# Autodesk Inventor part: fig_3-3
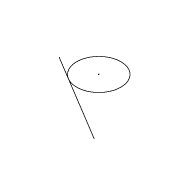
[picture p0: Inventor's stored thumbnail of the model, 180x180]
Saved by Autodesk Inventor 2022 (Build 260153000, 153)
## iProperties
Created: 2009-11
Part Number: fig_3-3
Document SubType Name: Modeling
Designer: Sham
Density: 1 g/cm^3
Material: Generic
Appearance: Default
Author: Sham
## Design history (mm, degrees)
sketch "Sketch1"
  geometry: L1 (-21, -10.296)-(20, -35); C1 r 10.296 at (-4.831, -8.018)
  constraints: 2 end point, 1 centre point, 1 tangent, 1 other
